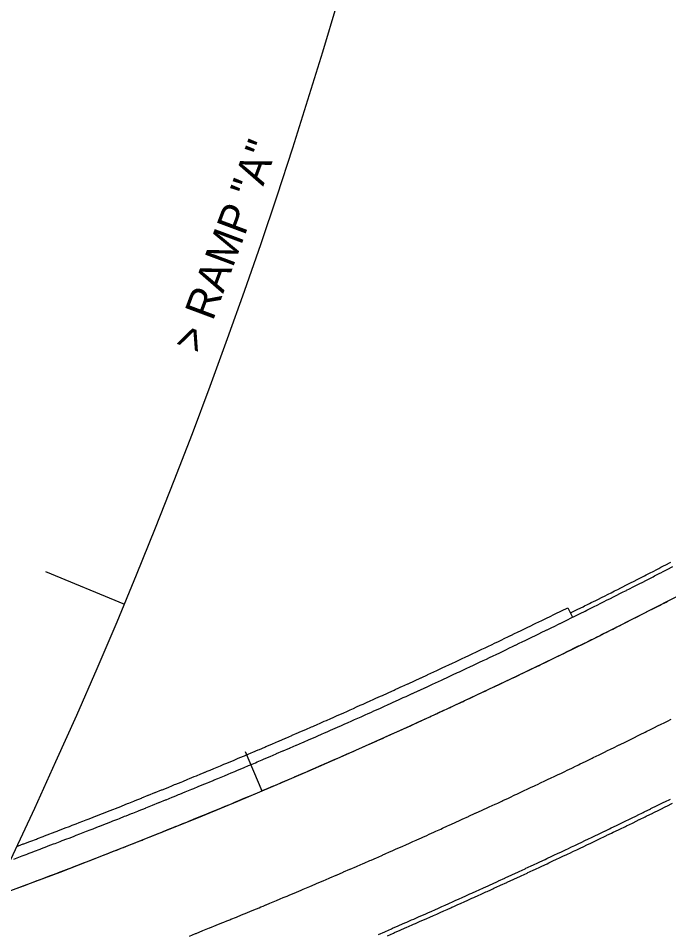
# Model space of a CAD drawing. Extents: x 2145147 to 2158018, y 137519 to 148068.
# Drawn here: x 2151382.1 to 2151473.5, y 142389.2 to 142517.8 of the extents above; entities that cross this region are included whole.
import ezdxf

# ---------------------------------------------------------------- set-up
doc = ezdxf.new("R2010")
doc.units = 0
for name, color, linetype in [('PR_Align_Ramp_A', 7, 'Continuous'), ('PR_Align_Ramp_A_Label', 7, 'Continuous'), ('PR_Align_Ramp_B', 7, 'Continuous'), ('PR_Phasing_Pavement_1', 7, 'Continuous')]:
    doc.layers.add(name, color=color, linetype=linetype)

msp = doc.modelspace()

# ---------------------------------------------------------------- linework, layer by layer
at = {"layer": 'PR_Align_Ramp_A'}
msp.add_lwpolyline([(2151385.93, 142440.09), (2151397.01, 142435.47)], dxfattribs=at)
msp.add_arc((2150641.52, 142750.44), 818.51, 334.17196, 99.86808, dxfattribs=at)
at = {"layer": 'PR_Align_Ramp_B'}
msp.add_lwpolyline([(2151413.97, 142414.76), (2151416.31, 142409.24)], dxfattribs=at)
msp.add_arc((2151085.75, 143191.05), 848.83, 280.66935, 303.94985, dxfattribs=at)
at = {"layer": 'PR_Phasing_Pavement_1'}
msp.add_line((2151459.32, 142434.99), (2151459.99, 142433.64), dxfattribs=at)
for points in [[(2151459.69, 142434.24), (2151459.83, 142434.3), (2151460.58, 142434.68), (2151460.76, 142434.77), (2151461.48, 142435.12), (2151461.7, 142435.23), (2151462.09, 142435.43), (2151462.37, 142435.56), (2151462.64, 142435.7), (2151463.26, 142436.01), (2151463.57, 142436.16), (2151464.15, 142436.45), (2151464.5, 142436.63), (2151465.03, 142436.9), (2151465.44, 142437.1), (2151465.92, 142437.35), (2151466.37, 142437.57), (2151466.81, 142437.8), (2151467.27, 142438.03), (2151467.3, 142438.05), (2151467.7, 142438.24), (2151468.24, 142438.52), (2151468.58, 142438.69), (2151469.17, 142438.99), (2151469.47, 142439.15), (2151470.1, 142439.47), (2151470.35, 142439.6), (2151471.03, 142439.94), (2151471.24, 142440.05), (2151471.96, 142440.42), (2151472.12, 142440.51), (2151472.43, 142440.67), (2151472.89, 142440.9), (2151473.01, 142440.96), (2151473.82, 142441.38)], [(2151459.99, 142433.64), (2151460.12, 142433.71), (2151460.88, 142434.08), (2151461.06, 142434.17), (2151461.77, 142434.52), (2151462, 142434.63), (2151462.39, 142434.83), (2151462.66, 142434.97), (2151462.93, 142435.1), (2151463.55, 142435.41), (2151463.87, 142435.57), (2151464.44, 142435.86), (2151464.8, 142436.04), (2151465.33, 142436.3), (2151465.74, 142436.51), (2151466.22, 142436.75), (2151466.67, 142436.98), (2151467.11, 142437.2), (2151467.57, 142437.43), (2151467.61, 142437.45), (2151468, 142437.65), (2151468.54, 142437.92), (2151468.89, 142438.1), (2151469.47, 142438.4), (2151469.77, 142438.55), (2151470.4, 142438.88), (2151470.66, 142439.01), (2151471.33, 142439.35), (2151471.54, 142439.46), (2151472.26, 142439.83), (2151472.43, 142439.91), (2151472.74, 142440.07), (2151473.19, 142440.31), (2151473.31, 142440.37), (2151474.12, 142440.79)], [(2151381.93, 142395.57), (2151382.83, 142395.91), (2151382.86, 142395.92), (2151383.8, 142396.27), (2151383.81, 142396.28), (2151384.06, 142396.37), (2151384.73, 142396.63), (2151384.8, 142396.65), (2151385.67, 142396.98), (2151385.78, 142397.02), (2151386.61, 142397.33), (2151386.76, 142397.39), (2151387.54, 142397.69), (2151387.75, 142397.77), (2151388.48, 142398.05), (2151388.73, 142398.14), (2151389.41, 142398.4), (2151389.51, 142398.44), (2151389.71, 142398.52), (2151390.34, 142398.76), (2151390.69, 142398.89), (2151391.28, 142399.12), (2151391.67, 142399.27), (2151392.21, 142399.48), (2151392.65, 142399.65), (2151393.14, 142399.84), (2151393.63, 142400.03), (2151394.07, 142400.2), (2151394.61, 142400.41), (2151394.94, 142400.54), (2151395, 142400.57), (2151395.59, 142400.8), (2151395.94, 142400.93), (2151396.57, 142401.18), (2151396.87, 142401.3), (2151397.55, 142401.57), (2151397.8, 142401.67), (2151398.52, 142401.95), (2151398.73, 142402.03), (2151399.5, 142402.34), (2151399.66, 142402.4), (2151400.36, 142402.68), (2151400.48, 142402.73), (2151400.58, 142402.77), (2151401.45, 142403.12), (2151401.51, 142403.14), (2151402.43, 142403.51), (2151402.44, 142403.52), (2151403.37, 142403.89), (2151403.4, 142403.9), (2151404.3, 142404.27), (2151404.38, 142404.3), (2151405.22, 142404.64), (2151405.35, 142404.69), (2151405.77, 142404.86), (2151406.15, 142405.02), (2151406.32, 142405.09), (2151407.07, 142405.4), (2151407.3, 142405.49), (2151408, 142405.78), (2151408.27, 142405.89), (2151408.92, 142406.16), (2151409.24, 142406.29), (2151409.85, 142406.54), (2151410.21, 142406.69), (2151410.45, 142406.79), (2151410.46, 142406.79), (2151410.77, 142406.92), (2151411.16, 142407.08), (2151411.18, 142407.09), (2151411.7, 142407.3), (2151412.15, 142407.49), (2151412.62, 142407.69), (2151413.12, 142407.9), (2151413.54, 142408.07), (2151414.09, 142408.3), (2151414.46, 142408.46), (2151415.06, 142408.71), (2151415.39, 142408.85), (2151416.03, 142409.12), (2151416.31, 142409.24), (2151416.53, 142409.33), (2151417, 142409.53), (2151417.23, 142409.63), (2151417.97, 142409.94), (2151418.15, 142410.02), (2151418.93, 142410.35), (2151419.07, 142410.41), (2151419.9, 142410.77), (2151419.99, 142410.8), (2151420.87, 142411.18), (2151420.91, 142411.2), (2151421.83, 142411.59), (2151421.83, 142411.6), (2151421.89, 142411.62), (2151422.74, 142411.99), (2151422.8, 142412.01), (2151423.66, 142412.39), (2151423.76, 142412.43), (2151424.58, 142412.79), (2151424.72, 142412.85), (2151425.49, 142413.19), (2151425.69, 142413.27), (2151426.41, 142413.59), (2151426.65, 142413.69), (2151427.23, 142413.95), (2151427.33, 142413.99), (2151427.61, 142414.11), (2151428.24, 142414.39), (2151428.57, 142414.54), (2151429.16, 142414.8), (2151429.54, 142414.96), (2151430.07, 142415.2), (2151430.5, 142415.39), (2151430.98, 142415.61), (2151431.46, 142415.82), (2151431.9, 142416.01), (2151432.42, 142416.24), (2151432.56, 142416.31), (2151432.81, 142416.42), (2151433.38, 142416.67), (2151433.72, 142416.83), (2151434.33, 142417.11), (2151434.64, 142417.24), (2151435.29, 142417.54), (2151435.55, 142417.65), (2151436.25, 142417.97), (2151436.46, 142418.07), (2151437.21, 142418.41), (2151437.37, 142418.48), (2151437.87, 142418.71), (2151438.16, 142418.84), (2151438.28, 142418.89), (2151439.12, 142419.28), (2151439.19, 142419.31), (2151440.07, 142419.72), (2151440.1, 142419.73), (2151441, 142420.14), (2151441.03, 142420.16), (2151441.91, 142420.57), (2151441.98, 142420.6), (2151442.82, 142420.98), (2151442.94, 142421.04), (2151443.17, 142421.14), (2151443.73, 142421.41), (2151443.89, 142421.48), (2151444.63, 142421.83), (2151444.84, 142421.93), (2151445.54, 142422.25), (2151445.8, 142422.37), (2151446.44, 142422.68), (2151446.75, 142422.82), (2151447.35, 142423.1), (2151447.7, 142423.27), (2151448.25, 142423.53), (2151448.44, 142423.62), (2151448.65, 142423.71), (2151449.16, 142423.95), (2151449.6, 142424.16), (2151450.06, 142424.38), (2151450.55, 142424.61), (2151450.96, 142424.81), (2151451.5, 142425.07), (2151451.87, 142425.24), (2151452.44, 142425.52), (2151452.77, 142425.68), (2151453.39, 142425.97), (2151453.67, 142426.11), (2151453.7, 142426.12), (2151454.34, 142426.43), (2151454.57, 142426.54), (2151455.29, 142426.89), (2151455.47, 142426.98), (2151456.23, 142427.35), (2151456.37, 142427.41), (2151457.18, 142427.81), (2151457.27, 142427.85), (2151458.12, 142428.27), (2151458.17, 142428.29), (2151458.95, 142428.67), (2151459.07, 142428.73), (2151459.07, 142428.73), (2151459.97, 142429.17), (2151460.01, 142429.19), (2151460.86, 142429.61), (2151460.95, 142429.65), (2151461.76, 142430.05), (2151461.9, 142430.12), (2151462.66, 142430.5), (2151462.84, 142430.59), (2151463.55, 142430.94), (2151463.78, 142431.05), (2151464.17, 142431.25), (2151464.45, 142431.39), (2151464.72, 142431.52), (2151465.34, 142431.83), (2151465.66, 142431.99), (2151466.24, 142432.28), (2151466.6, 142432.46), (2151467.13, 142432.73), (2151467.54, 142432.94), (2151468.02, 142433.18), (2151468.48, 142433.41), (2151468.92, 142433.63), (2151469.38, 142433.87), (2151469.42, 142433.88), (2151469.81, 142434.08), (2151470.35, 142434.36), (2151470.7, 142434.54), (2151471.29, 142434.84), (2151471.59, 142434.99), (2151472.22, 142435.31), (2151472.48, 142435.44), (2151473.16, 142435.79), (2151473.37, 142435.9), (2151474.1, 142436.27)], [(2151381.88, 142401.43), (2151382.13, 142401.53), (2151382.8, 142401.78), (2151382.86, 142401.8), (2151383.73, 142402.13), (2151383.84, 142402.17), (2151384.66, 142402.48), (2151384.81, 142402.54), (2151385.58, 142402.83), (2151385.79, 142402.91), (2151386.51, 142403.19), (2151386.76, 142403.28), (2151387.44, 142403.54), (2151387.54, 142403.58), (2151387.74, 142403.66), (2151388.37, 142403.9), (2151388.71, 142404.03), (2151389.3, 142404.25), (2151389.69, 142404.41), (2151390.22, 142404.61), (2151390.66, 142404.78), (2151391.15, 142404.97), (2151391.64, 142405.16), (2151392.07, 142405.33), (2151392.61, 142405.54), (2151392.94, 142405.67), (2151393, 142405.69), (2151393.58, 142405.92), (2151393.92, 142406.06), (2151394.55, 142406.3), (2151394.85, 142406.42), (2151395.52, 142406.69), (2151395.77, 142406.78), (2151396.49, 142407.07), (2151396.7, 142407.15), (2151397.47, 142407.45), (2151397.62, 142407.52), (2151398.32, 142407.8), (2151398.44, 142407.84), (2151398.54, 142407.88), (2151399.41, 142408.23), (2151399.47, 142408.25), (2151400.37, 142408.62), (2151400.39, 142408.62), (2151401.31, 142409), (2151401.34, 142409.01), (2151402.23, 142409.37), (2151402.31, 142409.4), (2151403.15, 142409.74), (2151403.28, 142409.79), (2151403.69, 142409.96), (2151404.07, 142410.12), (2151404.25, 142410.19), (2151404.99, 142410.49), (2151405.21, 142410.58), (2151405.91, 142410.87), (2151406.18, 142410.98), (2151406.83, 142411.25), (2151407.14, 142411.37), (2151407.75, 142411.62), (2151408.11, 142411.77), (2151408.34, 142411.87), (2151408.35, 142411.87), (2151408.67, 142412), (2151409.05, 142412.16), (2151409.07, 142412.17), (2151409.58, 142412.38), (2151410.04, 142412.57), (2151410.5, 142412.77), (2151411, 142412.98), (2151411.42, 142413.15), (2151411.97, 142413.38), (2151412.33, 142413.53), (2151412.93, 142413.78), (2151413.25, 142413.92), (2151413.89, 142414.19), (2151414.16, 142414.31), (2151414.39, 142414.4), (2151414.85, 142414.6), (2151415.08, 142414.69), (2151415.81, 142415), (2151415.99, 142415.08), (2151416.77, 142415.41), (2151416.91, 142415.47), (2151417.73, 142415.82), (2151417.82, 142415.86), (2151418.69, 142416.24), (2151418.73, 142416.25), (2151419.65, 142416.65), (2151419.65, 142416.65), (2151419.71, 142416.67), (2151420.56, 142417.04), (2151420.61, 142417.06), (2151421.47, 142417.44), (2151421.57, 142417.48), (2151422.38, 142417.83), (2151422.53, 142417.89), (2151423.29, 142418.23), (2151423.48, 142418.31), (2151424.2, 142418.63), (2151424.44, 142418.73), (2151425.02, 142418.99), (2151425.11, 142419.03), (2151425.4, 142419.15), (2151426.02, 142419.43), (2151426.35, 142419.57), (2151426.93, 142419.83), (2151427.31, 142419.99), (2151427.84, 142420.23), (2151428.26, 142420.42), (2151428.75, 142420.63), (2151429.22, 142420.84), (2151429.65, 142421.04), (2151430.17, 142421.27), (2151430.31, 142421.33), (2151430.56, 142421.44), (2151431.12, 142421.7), (2151431.47, 142421.85), (2151432.07, 142422.12), (2151432.37, 142422.26), (2151433.03, 142422.55), (2151433.28, 142422.67), (2151433.98, 142422.98), (2151434.18, 142423.08), (2151434.93, 142423.42), (2151435.09, 142423.49), (2151435.59, 142423.72), (2151435.88, 142423.85), (2151435.99, 142423.9), (2151436.83, 142424.28), (2151436.9, 142424.31), (2151437.78, 142424.72), (2151437.8, 142424.73), (2151438.7, 142425.14), (2151438.73, 142425.15), (2151439.6, 142425.56), (2151439.67, 142425.59), (2151440.51, 142425.98), (2151440.62, 142426.03), (2151440.85, 142426.14), (2151441.41, 142426.4), (2151441.57, 142426.47), (2151442.31, 142426.82), (2151442.52, 142426.91), (2151443.21, 142427.24), (2151443.46, 142427.35), (2151444.11, 142427.66), (2151444.41, 142427.8), (2151445.01, 142428.08), (2151445.35, 142428.24), (2151445.9, 142428.5), (2151446.09, 142428.59), (2151446.3, 142428.69), (2151446.8, 142428.93), (2151447.24, 142429.14), (2151447.7, 142429.35), (2151448.18, 142429.58), (2151448.6, 142429.78), (2151449.13, 142430.03), (2151449.49, 142430.21), (2151450.07, 142430.48), (2151450.39, 142430.64), (2151451.01, 142430.94), (2151451.29, 142431.07), (2151451.32, 142431.08), (2151451.95, 142431.39), (2151452.18, 142431.5), (2151452.89, 142431.84), (2151453.08, 142431.93), (2151453.83, 142432.3), (2151453.97, 142432.37), (2151454.77, 142432.75), (2151454.86, 142432.8), (2151455.71, 142433.21), (2151455.76, 142433.24), (2151456.53, 142433.61), (2151456.65, 142433.67), (2151456.65, 142433.67), (2151457.54, 142434.11), (2151457.58, 142434.13), (2151458.43, 142434.55), (2151459.32, 142434.99)], [(2151381.46, 142399.67), (2151382.4, 142400.02), (2151382.41, 142400.02), (2151382.65, 142400.11), (2151383.33, 142400.37), (2151383.39, 142400.39), (2151384.26, 142400.72), (2151384.37, 142400.76), (2151385.19, 142401.07), (2151385.35, 142401.13), (2151386.12, 142401.42), (2151386.32, 142401.5), (2151387.05, 142401.78), (2151387.3, 142401.87), (2151387.98, 142402.13), (2151388.08, 142402.17), (2151388.28, 142402.25), (2151388.91, 142402.49), (2151389.26, 142402.62), (2151389.84, 142402.85), (2151390.23, 142403), (2151390.77, 142403.21), (2151391.21, 142403.38), (2151391.69, 142403.57), (2151392.18, 142403.76), (2151392.62, 142403.93), (2151393.16, 142404.14), (2151393.49, 142404.27), (2151393.55, 142404.29), (2151394.13, 142404.52), (2151394.48, 142404.65), (2151395.1, 142404.9), (2151395.4, 142405.02), (2151396.08, 142405.28), (2151396.33, 142405.38), (2151397.05, 142405.67), (2151397.25, 142405.75), (2151398.02, 142406.05), (2151398.18, 142406.12), (2151398.88, 142406.4), (2151398.99, 142406.44), (2151399.1, 142406.49), (2151399.97, 142406.83), (2151400.03, 142406.86), (2151400.94, 142407.22), (2151400.95, 142407.23), (2151401.87, 142407.6), (2151401.91, 142407.61), (2151402.8, 142407.97), (2151402.88, 142408), (2151403.72, 142408.34), (2151403.85, 142408.4), (2151404.26, 142408.57), (2151404.64, 142408.72), (2151404.81, 142408.79), (2151405.56, 142409.1), (2151405.78, 142409.19), (2151406.48, 142409.47), (2151406.75, 142409.58), (2151407.4, 142409.85), (2151407.72, 142409.98), (2151408.32, 142410.23), (2151408.69, 142410.38), (2151408.92, 142410.48), (2151408.93, 142410.48), (2151409.24, 142410.61), (2151409.63, 142410.77), (2151409.65, 142410.78), (2151410.16, 142410.99), (2151410.62, 142411.18), (2151411.08, 142411.38), (2151411.58, 142411.59), (2151412, 142411.76), (2151412.55, 142411.99), (2151412.92, 142412.15), (2151413.51, 142412.4), (2151413.83, 142412.53), (2151414.48, 142412.8), (2151414.75, 142412.92), (2151414.97, 142413.01), (2151415.44, 142413.21), (2151415.67, 142413.31), (2151416.4, 142413.62), (2151416.58, 142413.7), (2151417.36, 142414.03), (2151417.5, 142414.09), (2151418.33, 142414.44), (2151418.41, 142414.48), (2151419.29, 142414.85), (2151419.33, 142414.87), (2151420.24, 142415.26), (2151420.25, 142415.27), (2151420.31, 142415.29), (2151421.16, 142415.66), (2151421.21, 142415.68), (2151422.07, 142416.05), (2151422.17, 142416.1), (2151422.98, 142416.45), (2151423.13, 142416.51), (2151423.9, 142416.85), (2151424.09, 142416.93), (2151424.81, 142417.25), (2151425.05, 142417.35), (2151425.63, 142417.61), (2151425.72, 142417.65), (2151426, 142417.77), (2151426.63, 142418.05), (2151426.96, 142418.19), (2151427.54, 142418.45), (2151427.92, 142418.62), (2151428.45, 142418.85), (2151428.87, 142419.04), (2151429.36, 142419.26), (2151429.83, 142419.47), (2151430.27, 142419.66), (2151430.78, 142419.89), (2151430.93, 142419.96), (2151431.18, 142420.07), (2151431.74, 142420.32), (2151432.09, 142420.48), (2151432.69, 142420.75), (2151432.99, 142420.89), (2151433.65, 142421.18), (2151433.9, 142421.3), (2151434.6, 142421.61), (2151434.81, 142421.71), (2151435.55, 142422.04), (2151435.71, 142422.12), (2151436.21, 142422.35), (2151436.5, 142422.48), (2151436.62, 142422.53), (2151437.46, 142422.91), (2151437.52, 142422.94), (2151438.41, 142423.35), (2151438.43, 142423.36), (2151439.33, 142423.78), (2151439.36, 142423.79), (2151440.24, 142424.19), (2151440.31, 142424.22), (2151441.14, 142424.61), (2151441.26, 142424.66), (2151441.48, 142424.77), (2151442.04, 142425.03), (2151442.2, 142425.11), (2151442.94, 142425.45), (2151443.15, 142425.55), (2151443.85, 142425.87), (2151444.1, 142425.99), (2151444.75, 142426.29), (2151445.05, 142426.43), (2151445.65, 142426.72), (2151445.99, 142426.88), (2151446.55, 142427.14), (2151446.74, 142427.23), (2151446.94, 142427.33), (2151447.45, 142427.57), (2151447.89, 142427.77), (2151448.35, 142427.99), (2151448.83, 142428.22), (2151449.25, 142428.42), (2151449.77, 142428.67), (2151450.14, 142428.85), (2151450.72, 142429.13), (2151451.04, 142429.28), (2151451.66, 142429.58), (2151451.94, 142429.71), (2151451.97, 142429.73), (2151452.6, 142430.03), (2151452.84, 142430.14), (2151453.55, 142430.49), (2151453.73, 142430.58), (2151454.49, 142430.94), (2151454.63, 142431.01), (2151455.43, 142431.4), (2151455.52, 142431.45), (2151456.37, 142431.86), (2151456.42, 142431.88), (2151457.19, 142432.26), (2151457.31, 142432.32), (2151457.31, 142432.32), (2151458.2, 142432.76), (2151458.25, 142432.78), (2151459.1, 142433.2), (2151459.99, 142433.64)], [(2151406.15, 142388.84), (2151407.03, 142389.2), (2151407.09, 142389.22), (2151408.02, 142389.6), (2151408.04, 142389.6), (2151408.98, 142389.98), (2151409.02, 142389.99), (2151409.92, 142390.36), (2151410.01, 142390.4), (2151410.87, 142390.74), (2151411, 142390.8), (2151411.42, 142390.97), (2151411.81, 142391.13), (2151411.99, 142391.2), (2151412.75, 142391.51), (2151412.98, 142391.61), (2151413.69, 142391.9), (2151413.97, 142392.01), (2151414.64, 142392.29), (2151414.96, 142392.42), (2151415.58, 142392.67), (2151415.95, 142392.83), (2151416.19, 142392.93), (2151416.2, 142392.93), (2151416.52, 142393.06), (2151416.91, 142393.22), (2151416.94, 142393.24), (2151417.46, 142393.45), (2151417.92, 142393.65), (2151418.4, 142393.85), (2151418.91, 142394.06), (2151419.33, 142394.24), (2151419.9, 142394.47), (2151420.27, 142394.63), (2151420.88, 142394.89), (2151421.21, 142395.02), (2151421.87, 142395.3), (2151422.15, 142395.42), (2151422.38, 142395.52), (2151422.85, 142395.72), (2151423.09, 142395.82), (2151423.84, 142396.14), (2151424.02, 142396.22), (2151424.82, 142396.56), (2151424.96, 142396.61), (2151425.8, 142396.98), (2151425.9, 142397.02), (2151426.79, 142397.4), (2151426.83, 142397.42), (2151427.76, 142397.82), (2151427.77, 142397.82), (2151427.83, 142397.85), (2151428.7, 142398.22), (2151428.75, 142398.25), (2151429.63, 142398.63), (2151429.73, 142398.67), (2151430.57, 142399.03), (2151430.71, 142399.1), (2151431.5, 142399.44), (2151431.69, 142399.52), (2151432.43, 142399.85), (2151432.67, 142399.95), (2151433.27, 142400.21), (2151433.36, 142400.26), (2151433.65, 142400.38), (2151434.29, 142400.67), (2151434.63, 142400.82), (2151435.23, 142401.08), (2151435.61, 142401.25), (2151436.16, 142401.49), (2151436.59, 142401.68), (2151437.09, 142401.9), (2151437.57, 142402.12), (2151438.02, 142402.32), (2151438.54, 142402.55), (2151438.69, 142402.62), (2151438.94, 142402.73), (2151439.52, 142402.99), (2151439.87, 142403.15), (2151440.49, 142403.43), (2151440.8, 142403.57), (2151441.47, 142403.87), (2151441.73, 142403.99), (2151442.44, 142404.31), (2151442.66, 142404.41), (2151443.42, 142404.75), (2151443.58, 142404.83), (2151444.1, 142405.06), (2151444.39, 142405.2), (2151444.51, 142405.25), (2151445.36, 142405.64), (2151445.43, 142405.67), (2151446.34, 142406.09), (2151446.36, 142406.1), (2151447.28, 142406.52), (2151447.31, 142406.53), (2151448.21, 142406.95), (2151448.28, 142406.98), (2151449.13, 142407.38), (2151449.25, 142407.43), (2151449.48, 142407.54), (2151450.05, 142407.8), (2151450.22, 142407.88), (2151450.98, 142408.23), (2151451.19, 142408.33), (2151451.9, 142408.67), (2151452.16, 142408.79), (2151452.82, 142409.1), (2151453.13, 142409.24), (2151453.74, 142409.53), (2151454.09, 142409.7), (2151454.66, 142409.96), (2151454.85, 142410.05), (2151455.06, 142410.15), (2151455.58, 142410.4), (2151456.03, 142410.61), (2151456.5, 142410.84), (2151456.99, 142411.07), (2151457.42, 142411.27), (2151457.96, 142411.53), (2151458.34, 142411.71), (2151458.92, 142411.99), (2151459.25, 142412.15), (2151459.89, 142412.45), (2151460.17, 142412.59), (2151460.21, 142412.61), (2151460.85, 142412.92), (2151461.09, 142413.03), (2151461.82, 142413.38), (2151462.01, 142413.48), (2151462.78, 142413.85), (2151462.92, 142413.92), (2151463.74, 142414.32), (2151463.84, 142414.36), (2151464.7, 142414.79), (2151464.75, 142414.81), (2151465.54, 142415.2), (2151465.66, 142415.26), (2151465.67, 142415.26), (2151466.58, 142415.71), (2151466.62, 142415.73), (2151467.49, 142416.15), (2151467.58, 142416.2), (2151468.41, 142416.6), (2151468.54, 142416.67), (2151469.32, 142417.06), (2151469.5, 142417.15), (2151470.23, 142417.51), (2151470.46, 142417.62), (2151470.86, 142417.82), (2151471.14, 142417.96), (2151471.42, 142418.1), (2151472.05, 142418.42), (2151472.37, 142418.58), (2151472.96, 142418.87), (2151473.33, 142419.06), (2151473.87, 142419.33)], [(2151432.72, 142389.07), (2151433.61, 142389.45), (2151433.72, 142389.5), (2151434.56, 142389.86), (2151434.71, 142389.93), (2151435.5, 142390.27), (2151435.7, 142390.36), (2151436.44, 142390.69), (2151436.69, 142390.8), (2151437.29, 142391.06), (2151437.39, 142391.1), (2151437.68, 142391.23), (2151438.33, 142391.52), (2151438.67, 142391.67), (2151439.27, 142391.93), (2151439.66, 142392.1), (2151440.21, 142392.35), (2151440.65, 142392.54), (2151441.15, 142392.77), (2151441.64, 142392.98), (2151442.09, 142393.19), (2151442.63, 142393.42), (2151442.78, 142393.49), (2151443.03, 142393.61), (2151443.61, 142393.87), (2151443.97, 142394.03), (2151444.6, 142394.31), (2151444.91, 142394.45), (2151445.59, 142394.76), (2151445.85, 142394.88), (2151446.57, 142395.2), (2151446.79, 142395.3), (2151447.56, 142395.65), (2151447.72, 142395.73), (2151448.24, 142395.96), (2151448.54, 142396.1), (2151448.66, 142396.15), (2151449.53, 142396.55), (2151449.6, 142396.58), (2151450.51, 142397), (2151450.53, 142397.01), (2151451.47, 142397.44), (2151451.49, 142397.45), (2151452.4, 142397.87), (2151452.48, 142397.91), (2151453.34, 142398.3), (2151453.46, 142398.36), (2151453.69, 142398.47), (2151454.27, 142398.74), (2151454.44, 142398.82), (2151455.2, 142399.17), (2151455.42, 142399.27), (2151456.14, 142399.61), (2151456.4, 142399.73), (2151457.07, 142400.05), (2151457.38, 142400.19), (2151458, 142400.48), (2151458.36, 142400.65), (2151458.93, 142400.92), (2151459.13, 142401.01), (2151459.34, 142401.11), (2151459.86, 142401.36), (2151460.31, 142401.58), (2151460.79, 142401.8), (2151461.29, 142402.04), (2151461.72, 142402.25), (2151462.27, 142402.51), (2151462.65, 142402.69), (2151463.24, 142402.97), (2151463.58, 142403.13), (2151464.22, 142403.44), (2151464.51, 142403.58), (2151464.54, 142403.6), (2151465.19, 142403.91), (2151465.44, 142404.03), (2151466.17, 142404.38), (2151466.36, 142404.47), (2151467.14, 142404.85), (2151467.29, 142404.92), (2151468.12, 142405.33), (2151468.21, 142405.37), (2151469.09, 142405.8), (2151469.14, 142405.82), (2151469.94, 142406.22), (2151470.06, 142406.28), (2151470.06, 142406.28), (2151470.99, 142406.73), (2151471.03, 142406.75), (2151471.91, 142407.18), (2151472, 142407.23), (2151472.83, 142407.64), (2151472.97, 142407.71), (2151473.76, 142408.1)], [(2151433.98, 142388.89), (2151434.82, 142389.25), (2151434.97, 142389.32), (2151435.77, 142389.66), (2151435.97, 142389.75), (2151436.71, 142390.08), (2151436.96, 142390.19), (2151437.56, 142390.45), (2151437.66, 142390.49), (2151437.95, 142390.62), (2151438.6, 142390.91), (2151438.94, 142391.06), (2151439.54, 142391.32), (2151439.93, 142391.5), (2151440.48, 142391.74), (2151440.92, 142391.93), (2151441.42, 142392.16), (2151441.91, 142392.38), (2151442.37, 142392.58), (2151442.9, 142392.82), (2151443.05, 142392.88), (2151443.31, 142393), (2151443.89, 142393.26), (2151444.25, 142393.42), (2151444.88, 142393.7), (2151445.19, 142393.84), (2151445.86, 142394.15), (2151446.12, 142394.27), (2151446.85, 142394.6), (2151447.06, 142394.69), (2151447.83, 142395.04), (2151448, 142395.12), (2151448.52, 142395.36), (2151448.82, 142395.49), (2151448.94, 142395.55), (2151449.8, 142395.94), (2151449.88, 142395.97), (2151450.79, 142396.39), (2151450.81, 142396.4), (2151451.75, 142396.83), (2151451.77, 142396.85), (2151452.68, 142397.27), (2151452.76, 142397.3), (2151453.62, 142397.7), (2151453.74, 142397.76), (2151453.97, 142397.86), (2151454.55, 142398.13), (2151454.72, 142398.21), (2151455.49, 142398.57), (2151455.7, 142398.67), (2151456.42, 142399.01), (2151456.68, 142399.13), (2151457.35, 142399.44), (2151457.66, 142399.59), (2151458.28, 142399.88), (2151458.64, 142400.05), (2151459.22, 142400.32), (2151459.41, 142400.41), (2151459.62, 142400.51), (2151460.15, 142400.76), (2151460.6, 142400.97), (2151461.08, 142401.2), (2151461.58, 142401.44), (2151462.01, 142401.64), (2151462.56, 142401.91), (2151462.94, 142402.09), (2151463.53, 142402.37), (2151463.87, 142402.53), (2151464.51, 142402.84), (2151464.8, 142402.98), (2151464.83, 142403), (2151465.48, 142403.31), (2151465.72, 142403.43), (2151466.46, 142403.78), (2151466.65, 142403.88), (2151467.43, 142404.25), (2151467.58, 142404.32), (2151468.41, 142404.73), (2151468.51, 142404.77), (2151469.38, 142405.2), (2151469.43, 142405.23), (2151470.23, 142405.62), (2151470.35, 142405.68), (2151470.36, 142405.68), (2151471.28, 142406.13), (2151471.33, 142406.15), (2151472.21, 142406.59), (2151472.3, 142406.63), (2151473.13, 142407.04), (2151473.27, 142407.11), (2151474.05, 142407.5)]]:
    msp.add_lwpolyline(points, dxfattribs=at)

# ---------------------------------------------------------------- texts
at = {"layer": 'PR_Align_Ramp_A_Label'}
msp.add_text('> RAMP "A"', height=4.3, rotation=69.522, dxfattribs=at).set_placement((2151407.7, 142470.54))

doc.saveas('drawing.dxf')
